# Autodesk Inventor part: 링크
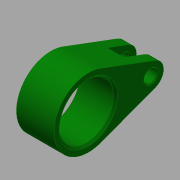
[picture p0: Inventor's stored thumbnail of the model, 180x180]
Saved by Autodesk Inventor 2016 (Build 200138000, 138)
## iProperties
Created: 2016-08
Part Number: 링크
Material: 강철, 탄소
Document SubType Name: Modeling
Designer: mduedu
Density: 7.87 g/cm^3
Appearance: 진녹색
Author: mduedu
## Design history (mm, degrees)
sketch "스케치1"
  geometry: L1 (32.1, 5.62)-(5.775, 15.456); L2 (32.1, -5.62)-(5.775, -15.456); C1 r 13 at (0, 0); C2 r 3 at (30, 0); A1 r 16.5 centre (0, 0) between (5.775, 15.456) and (5.775, -15.456); A2 r 6 centre (30, 0) between (32.1, 5.62) and (32.1, -5.62); 1 further point
  constraints: 4 centre point, 4 end point, 4 point on circle, 4 tangent, 3 coincident, 1 horizontal alignment
  dimensions: "d0" = 33 diameter of A1; "d2" = 12 diameter of A2; "d3" = 30 distance of A2.centre point (0, 0); "d4" = 26 diameter of C1; "d5" = 6 diameter of C2
extrude "돌출1" new body sketch "스케치1" stored distance "d6" = 18; taper "d7" = 0 deg
sketch "스케치2"
  geometry: L1 (-9, 36)-(9, 36) reference; L2 (0, 0)-(0, 36); L3 (-4, 36)-(4, 36); L4 (4, 36)-(4, 22); L5 (4, 22)-(-4, 22); L6 (-4, 22)-(-4, 36)
  constraints: 10 end point, 2 midpoint, 2 parallel, 1 horizontal, 1 perpendicular, 1 point on line
  dimensions: "d8" = 8 distance between parallel lines of L4 L6; "d10" = 14 distance of L3.end L4.end
extrude "돌출2" cut sketch "스케치2" stored distance "d11" = 20; taper "d12" = 0 deg
chamfer "모따기1" distance "d13" = 1; stored, may be unused: second distance "d14" = 2, angle "d15" = 45 deg
chamfer "모따기2" distance "d16" = 0.5; stored, may be unused: second distance "d17" = 2, angle "d18" = 45 deg
node "솔리드1"
